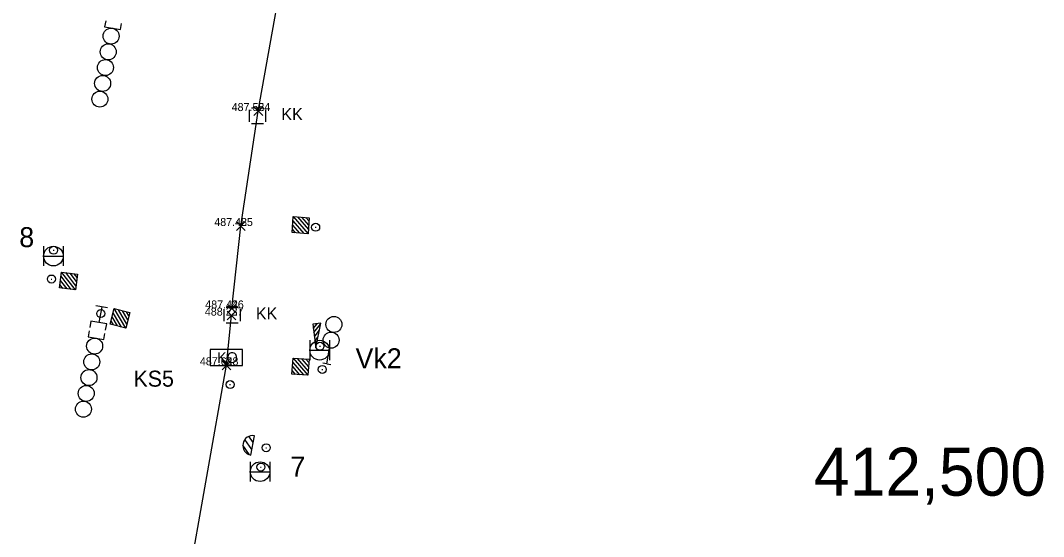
# Model space of a CAD drawing. Extents: x -874058 to -854960, y -10531873 to -1049126.
# Drawn here: x -866535.9 to -866408.1, y -1050167.1 to -1050102.6 of the extents above; entities that cross this region are included whole.
import ezdxf

# ---------------------------------------------------------------- set-up
doc = ezdxf.new("R2010")
doc.units = 0
for name, color, linetype in [('Vrstva 2', 7, 'Continuous'), ('Vrstva 28', 7, 'Continuous'), ('Vrstva 3', 7, 'Continuous'), ('Vrstva 32', 7, 'Continuous'), ('Vrstva 35', 7, 'Continuous'), ('Vrstva 50', 7, 'Continuous'), ('Vrstva 6', 7, 'Continuous'), ('Vrstva 60', 7, 'Continuous'), ('Vrstva 61', 7, 'Continuous'), ('Vrstva 7', 7, 'Continuous')]:
    doc.layers.add(name, color=color, linetype=linetype)

msp = doc.modelspace()

# ---------------------------------------------------------------- linework, layer by layer
at = {"layer": 'Vrstva 28'}
for p, q in [((-866508.2, -1050143.71), (-866512.24, -1050143.71)), ((-866512.24, -1050143.71), (-866512.24, -1050145.73)), ((-866508.2, -1050145.73), (-866508.2, -1050143.71)), ((-866512.24, -1050145.73), (-866508.2, -1050145.73))]:
    msp.add_line(p, q, dxfattribs=at)
at = {"layer": 'Vrstva 3'}
for p, q in [((-866501.92, -1050128.18), (-866501.05, -1050129.18)), ((-866501.88, -1050127.65), (-866500.52, -1050129.22)), ((-866501.85, -1050127.13), (-866499.99, -1050129.26)), ((-866501.32, -1050127.16), (-866499.95, -1050128.73)), ((-866500.79, -1050127.2), (-866499.92, -1050128.2)), ((-866500.26, -1050127.23), (-866499.88, -1050127.67)), ((-866501.96, -1050128.71), (-866501.58, -1050129.15)), ((-866533.04, -1050130.83), (-866533.04, -1050133.29)), ((-866530.58, -1050130.83), (-866530.58, -1050133.29)), ((-866533.04, -1050132.06), (-866530.58, -1050132.06)), ((-866529.59, -1050136.23), (-866530.86, -1050134.58)), ((-866529.06, -1050136.29), (-866530.79, -1050134.06)), ((-866529, -1050135.77), (-866530.27, -1050134.12)), ((-866528.93, -1050135.24), (-866529.74, -1050134.19)), ((-866528.86, -1050134.72), (-866529.22, -1050134.26)), ((-866530.64, -1050136.09), (-866530.99, -1050135.64)), ((-866530.11, -1050136.16), (-866530.93, -1050135.11)), ((-866523.8, -1050140.79), (-866524.48, -1050139.65)), ((-866523.29, -1050140.93), (-866524.34, -1050139.14)), ((-866522.78, -1050141.06), (-866524.21, -1050138.62)), ((-866522.64, -1050140.55), (-866523.7, -1050138.76)), ((-866522.51, -1050140.03), (-866523.18, -1050138.89)), ((-866522.38, -1050139.52), (-866522.67, -1050139.02)), ((-866524.32, -1050140.66), (-866524.61, -1050140.16)), ((-866499.39, -1050140.58), (-866499.37, -1050140.57)), ((-866499.33, -1050141.09), (-866498.85, -1050140.51)), ((-866499.26, -1050141.61), (-866498.43, -1050140.56)), ((-866499.2, -1050142.14), (-866498.6, -1050141.37)), ((-866499.14, -1050142.66), (-866498.76, -1050142.17)), ((-866499.77, -1050142.58), (-866499.77, -1050145.04)), ((-866499.07, -1050143.18), (-866498.93, -1050142.98)), ((-866497.31, -1050142.58), (-866497.31, -1050145.04)), ((-866501.87, -1050144.82), (-866500.01, -1050146.95)), ((-866501.34, -1050144.85), (-866499.97, -1050146.42)), ((-866500.81, -1050144.89), (-866499.94, -1050145.89)), ((-866500.28, -1050144.92), (-866499.9, -1050145.36)), ((-866499.77, -1050143.81), (-866497.31, -1050143.81)), ((-866501.94, -1050145.87), (-866501.07, -1050146.87)), ((-866501.9, -1050145.34), (-866500.54, -1050146.91)), ((-866501.98, -1050146.4), (-866501.6, -1050146.84)), ((-866507, -1050156.21), (-866507.87, -1050154.95)), ((-866506.84, -1050155.35), (-866507.39, -1050154.57)), ((-866507.14, -1050156.93), (-866506.69, -1050154.5)), ((-866506.69, -1050154.5), (-866506.69, -1050154.5)), ((-866506.69, -1050154.5), (-866506.69, -1050154.5)), ((-866507.29, -1050156.89), (-866508.13, -1050155.66)), ((-866507.21, -1050157.76), (-866507.21, -1050160.22)), ((-866507.21, -1050158.99), (-866504.75, -1050158.99)), ((-866504.75, -1050157.76), (-866504.75, -1050160.22))]:
    msp.add_line(p, q, dxfattribs=at)
for points in [[(-866499.85, -1050127.26), (-866499.99, -1050129.26), (-866501.98, -1050129.12), (-866501.85, -1050127.13)], [(-866499.85, -1050127.26), (-866499.99, -1050129.26), (-866501.98, -1050129.12), (-866501.85, -1050127.13)], [(-866531.05, -1050136.04), (-866530.79, -1050134.06), (-866528.81, -1050134.31), (-866529.06, -1050136.29)], [(-866531.05, -1050136.04), (-866530.79, -1050134.06), (-866528.81, -1050134.31), (-866529.06, -1050136.29)], [(-866524.71, -1050140.56), (-866524.21, -1050138.62), (-866522.27, -1050139.12), (-866522.78, -1050141.06)], [(-866524.71, -1050140.56), (-866524.21, -1050138.62), (-866522.27, -1050139.12), (-866522.78, -1050141.06)], [(-866499.87, -1050144.95), (-866500.01, -1050146.95), (-866502, -1050146.81), (-866501.87, -1050144.82)], [(-866499.87, -1050144.95), (-866500.01, -1050146.95), (-866502, -1050146.81), (-866501.87, -1050144.82)]]:
    msp.add_lwpolyline(points, close=True, dxfattribs=at)
for points in [[(-866499.85, -1050127.26), (-866499.99, -1050129.26), (-866501.98, -1050129.12), (-866501.85, -1050127.13), (-866499.85, -1050127.26)], [(-866499.85, -1050127.26), (-866499.99, -1050129.26), (-866501.98, -1050129.12), (-866501.85, -1050127.13), (-866499.85, -1050127.26)], [(-866531.05, -1050136.04), (-866530.79, -1050134.06), (-866528.81, -1050134.31), (-866529.06, -1050136.29), (-866531.05, -1050136.04)], [(-866531.05, -1050136.04), (-866530.79, -1050134.06), (-866528.81, -1050134.31), (-866529.06, -1050136.29), (-866531.05, -1050136.04)], [(-866524.71, -1050140.56), (-866524.21, -1050138.62), (-866522.27, -1050139.12), (-866522.78, -1050141.06), (-866524.71, -1050140.56)], [(-866524.71, -1050140.56), (-866524.21, -1050138.62), (-866522.27, -1050139.12), (-866522.78, -1050141.06), (-866524.71, -1050140.56)], [(-866499.03, -1050143.5), (-866498.41, -1050140.45), (-866499.39, -1050140.57), (-866499.03, -1050143.5)], [(-866499.03, -1050143.5), (-866498.41, -1050140.45), (-866499.39, -1050140.57), (-866499.03, -1050143.5)], [(-866499.87, -1050144.95), (-866500.01, -1050146.95), (-866502, -1050146.81), (-866501.87, -1050144.82), (-866499.87, -1050144.95)], [(-866499.87, -1050144.95), (-866500.01, -1050146.95), (-866502, -1050146.81), (-866501.87, -1050144.82), (-866499.87, -1050144.95)]]:
    msp.add_lwpolyline(points, dxfattribs=at)
for centre in [(-866531.81, -1050132.06), (-866498.54, -1050143.81), (-866505.98, -1050158.99)]:
    msp.add_circle(centre, 1.23, dxfattribs=at)
for start, end in [(79.4714, 169.4656), (169.4714, 259.4714)]:
    msp.add_arc((-866506.91, -1050155.71), 1.23, start, end, dxfattribs=at)
at = {"layer": 'Vrstva 32'}
for points in [[(-866509.51, -1050138.6), (-866508.38, -1050128.3), (-866506.21, -1050113.94), (-866501.87, -1050089.49), (-866497.28, -1050066.11), (-866497.1, -1050064.94), (-866497.46, -1050061.87), (-866494.3, -1050044.44), (-866492.93, -1050041.88), (-866492.72, -1050040.74), (-866490.75, -1050027.82), (-866490.32, -1050025.14), (-866485.86, -1049999.67), (-866484.76, -1049995.81), (-866484.48, -1049994.61), (-866483.95, -1049988.67), (-866480.26, -1049968.24), (-866479.04, -1049964.21), (-866475.22, -1049944.1), (-866474.75, -1049941.59)], [(-866521.22, -1050207.39), (-866517.57, -1050187.41), (-866510.18, -1050145.7), (-866509.56, -1050139.49)]]:
    msp.add_lwpolyline(points, dxfattribs=at)
at = {"layer": 'Vrstva 35'}
for p, q in [((-866507.3, -1050115.28), (-866507.3, -1050113.78)), ((-866507.05, -1050113.53), (-866505.55, -1050113.53)), ((-866505.3, -1050113.78), (-866505.3, -1050115.28)), ((-866505.55, -1050115.53), (-866507.05, -1050115.53)), ((-866510.23, -1050138.43), (-866508.73, -1050138.43)), ((-866510.48, -1050140.18), (-866510.48, -1050138.68)), ((-866508.48, -1050138.68), (-866508.48, -1050140.18)), ((-866508.73, -1050140.43), (-866510.23, -1050140.43))]:
    msp.add_line(p, q, dxfattribs=at)
at = {"layer": 'Vrstva 50'}
for p, q in [((-866499.09, -1050128.46), (-866498.99, -1050128.46)), ((-866531.84, -1050131.32), (-866531.74, -1050131.32)), ((-866532.11, -1050134.92), (-866532.01, -1050134.92)), ((-866525.94, -1050139.24), (-866525.84, -1050139.24)), ((-866498.55, -1050143.31), (-866498.45, -1050143.31)), ((-866498.26, -1050146.22), (-866498.16, -1050146.22)), ((-866505.27, -1050156), (-866505.17, -1050156)), ((-866505.94, -1050158.41), (-866505.84, -1050158.41))]:
    msp.add_line(p, q, dxfattribs=at)
for centre in [(-866499.04, -1050128.46), (-866531.79, -1050131.32), (-866532.06, -1050134.92), (-866525.89, -1050139.24), (-866498.5, -1050143.31), (-866498.21, -1050146.22), (-866505.22, -1050156), (-866505.89, -1050158.41)]:
    msp.add_circle(centre, 0.5, dxfattribs=at)
at = {"layer": 'Vrstva 6'}
for p, q in [((-866525.04, -1050138.51), (-866526.52, -1050138.25)), ((-866525.78, -1050138.38), (-866525.78, -1050138.38)), ((-866497.64, -1050145.51), (-866497.29, -1050143.54)), ((-866497.64, -1050145.51), (-866498.13, -1050145.42)), ((-866497.64, -1050145.51), (-866497.15, -1050145.6))]:
    msp.add_line(p, q, dxfattribs=at)
for points in [[(-866525.28, -1050102.66), (-866525.41, -1050103.41), (-866523.44, -1050103.76), (-866523.31, -1050103.01)], [(-866525.78, -1050138.38), (-866526.13, -1050140.35), (-866527.12, -1050140.17), (-866527.26, -1050140.96)], [(-866525.29, -1050141.31), (-866525.15, -1050140.53), (-866526.13, -1050140.35)], [(-866527.34, -1050141.39), (-866527.47, -1050142.14), (-866525.5, -1050142.49), (-866525.37, -1050141.74)]]:
    msp.add_lwpolyline(points, dxfattribs=at)
for centre in [(-866524.6, -1050104.57), (-866524.96, -1050106.54), (-866525.31, -1050108.51), (-866525.66, -1050110.48), (-866526.01, -1050112.45), (-866496.76, -1050140.59), (-866526.66, -1050143.3), (-866497.11, -1050142.56), (-866527.02, -1050145.27), (-866527.37, -1050147.24), (-866527.72, -1050149.21), (-866528.07, -1050151.18)]:
    msp.add_circle(centre, 1, dxfattribs=at)
at = {"layer": 'Vrstva 60'}
for p, q in [((-866506.76, -1050114.49), (-866505.66, -1050113.39)), ((-866505.66, -1050114.49), (-866506.76, -1050113.39)), ((-866508.93, -1050128.85), (-866507.83, -1050127.75)), ((-866507.83, -1050128.85), (-866508.93, -1050127.75)), ((-866510.06, -1050139.15), (-866508.96, -1050138.05)), ((-866508.96, -1050139.15), (-866510.06, -1050138.05)), ((-866510.11, -1050140.04), (-866509.01, -1050138.94)), ((-866509.01, -1050140.04), (-866510.11, -1050138.94)), ((-866510.73, -1050146.25), (-866509.63, -1050145.15)), ((-866509.63, -1050146.25), (-866510.73, -1050145.15))]:
    msp.add_line(p, q, dxfattribs=at)
at = {"layer": 'Vrstva 7'}
for p, q in [((-866509.79, -1050148.1), (-866509.69, -1050148.1)), ((-866509.77, -1050148.11), (-866509.67, -1050148.11))]:
    msp.add_line(p, q, dxfattribs=at)
for centre in [(-866509.74, -1050148.1), (-866509.72, -1050148.11)]:
    msp.add_circle(centre, 0.5, dxfattribs=at)

# ---------------------------------------------------------------- texts
at = {"layer": 'Vrstva 2'}
for s, p in [('8', (-866536.08, -1050130.94)), ('Vk2', (-866494.05, -1050146.07)), ('7', (-866502.19, -1050159.61))]:
    msp.add_text(s, height=2.5, dxfattribs=at).set_placement(p)
at = {"layer": 'Vrstva 28'}
for s, height, p in [('KO', 1.344, (-866511.37, -1050145.41)), ('KS5', 2, (-866521.81, -1050148.37))]:
    msp.add_text(s, height=height, dxfattribs=at).set_placement(p)
at = {"layer": 'Vrstva 35'}
for p in [(-866503.33, -1050115.07), (-866506.51, -1050139.97)]:
    msp.add_text('KK', height=1.5, dxfattribs=at).set_placement(p)
at = {"layer": 'Vrstva 60'}
for s, p in [('24', (-866506.21, -1050113.94)), ('25', (-866508.38, -1050128.3)), ('27', (-866509.56, -1050139.49)), ('26', (-866509.51, -1050138.6)), ('28', (-866510.18, -1050145.7))]:
    msp.add_text(s, height=1, dxfattribs=at).set_placement(p)
at = {"layer": 'Vrstva 61'}
for s, p in [('487.55 ', (-866509.54, -1050113.94)), ('487.48 ', (-866511.71, -1050128.3)), ('488.23 ', (-866512.89, -1050139.49)), ('487.44 ', (-866512.84, -1050138.6)), ('487.64 ', (-866513.51, -1050145.7))]:
    msp.add_text(s, height=1, dxfattribs=at).set_placement(p)
at = {"layer": 'Vrstva 7'}
msp.add_text('412,500', height=6, dxfattribs=at).set_placement((-866436.76, -1050161.99))

doc.saveas('drawing.dxf')
